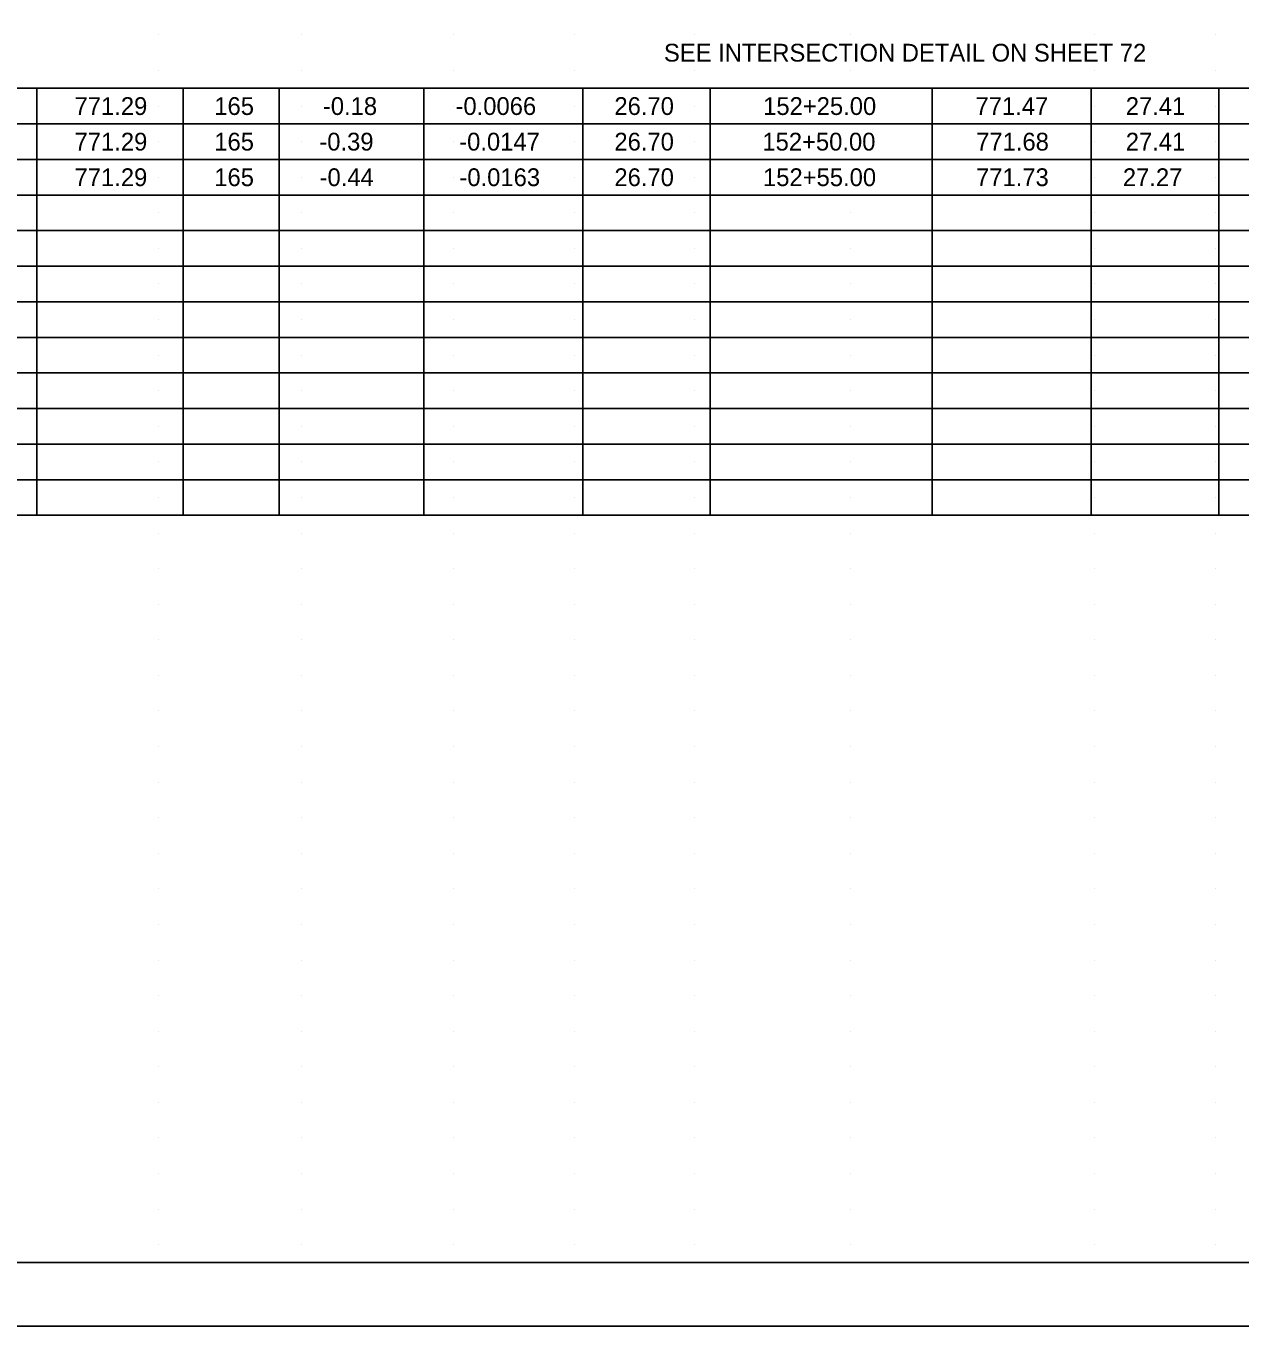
# Model space of a CAD drawing. Extents: x -15.4 to 18.6, y -12.6 to 9.4.
# Drawn here: x -5.6 to 3.96, y -12.61 to -2.38 of the extents above; entities that cross this region are included whole.
import ezdxf

# ---------------------------------------------------------------- set-up
doc = ezdxf.new("R2010")
doc.units = 0
for name, color, linetype in [('SH_Border', 7, 'Continuous'), ('SH_Cut_Line', 7, 'Continuous'), ('SH_Data', 7, 'Continuous'), ('SH_Text', 7, 'Continuous')]:
    doc.layers.add(name, color=color, linetype=linetype)

msp = doc.modelspace()

# ---------------------------------------------------------------- linework, layer by layer
at = {"layer": 'SH_Border'}
msp.add_lwpolyline([(-13.357, 8.888), (18.143, 8.888), (18.143, -12.112), (-13.357, -12.112)], close=True, dxfattribs=at)
at = {"layer": 'SH_Cut_Line'}
msp.add_lwpolyline([(-15.357, -12.612), (18.643, -12.612), (18.643, 9.388), (-15.357, 9.388)], close=True, dxfattribs=at)
at = {"layer": 'SH_Data'}
for p, q in [((-4.557, -2.452), (-4.557, -2.452)), ((-3.432, -2.452), (-3.432, -2.452)), ((-2.232, -2.452), (-2.232, -2.452)), ((-1.282, -2.452), (-1.282, -2.452)), ((-0.332, -2.452), (-0.332, -2.452)), ((0.893, -2.452), (0.893, -2.452)), ((2.818, -2.452), (2.818, -2.452)), ((3.768, -2.452), (3.768, -2.452)), ((-4.557, -2.732), (-4.557, -2.732)), ((-3.432, -2.732), (-3.432, -2.732)), ((-2.232, -2.732), (-2.232, -2.732)), ((-1.282, -2.732), (-1.282, -2.732)), ((-0.332, -2.732), (-0.332, -2.732)), ((0.893, -2.732), (0.893, -2.732)), ((2.818, -2.732), (2.818, -2.732)), ((3.768, -2.732), (3.768, -2.732)), ((-10.059, -2.872), (13.939, -2.872)), ((-5.513, -2.872), (-5.513, -6.232)), ((-4.36, -2.872), (-4.36, -6.232)), ((-3.603, -2.872), (-3.603, -6.232)), ((-2.466, -2.872), (-2.466, -6.232)), ((-1.214, -2.872), (-1.214, -6.232)), ((-0.21, -2.872), (-0.21, -6.232)), ((1.536, -2.872), (1.536, -6.232)), ((2.788, -2.872), (2.788, -6.232)), ((3.793, -2.872), (3.793, -6.232)), ((-4.557, -3.012), (-4.557, -3.012)), ((-3.432, -3.012), (-3.432, -3.012)), ((-2.232, -3.012), (-2.232, -3.012)), ((-1.282, -3.012), (-1.282, -3.012)), ((-0.332, -3.012), (-0.332, -3.012)), ((0.893, -3.012), (0.893, -3.012)), ((2.818, -3.012), (2.818, -3.012)), ((3.768, -3.012), (3.768, -3.012)), ((-10.059, -3.152), (13.939, -3.152)), ((-4.557, -3.292), (-4.557, -3.292)), ((-3.432, -3.292), (-3.432, -3.292)), ((-2.232, -3.292), (-2.232, -3.292)), ((-1.282, -3.292), (-1.282, -3.292)), ((-0.332, -3.292), (-0.332, -3.292)), ((0.893, -3.292), (0.893, -3.292)), ((2.818, -3.292), (2.818, -3.292)), ((3.768, -3.292), (3.768, -3.292)), ((-10.059, -3.432), (13.939, -3.432)), ((-4.557, -3.572), (-4.557, -3.572)), ((-3.432, -3.572), (-3.432, -3.572)), ((-2.232, -3.572), (-2.232, -3.572)), ((-1.282, -3.572), (-1.282, -3.572)), ((-0.332, -3.572), (-0.332, -3.572)), ((0.893, -3.572), (0.893, -3.572)), ((2.818, -3.572), (2.818, -3.572)), ((3.768, -3.572), (3.768, -3.572)), ((-10.059, -3.712), (13.939, -3.712)), ((-4.557, -3.852), (-4.557, -3.852)), ((-3.432, -3.852), (-3.432, -3.852)), ((-2.232, -3.852), (-2.232, -3.852)), ((-1.282, -3.852), (-1.282, -3.852)), ((-0.332, -3.852), (-0.332, -3.852)), ((0.893, -3.852), (0.893, -3.852)), ((2.818, -3.852), (2.818, -3.852)), ((3.768, -3.852), (3.768, -3.852)), ((-10.059, -3.992), (13.939, -3.992)), ((-4.557, -4.132), (-4.557, -4.132)), ((-3.432, -4.132), (-3.432, -4.132)), ((-2.232, -4.132), (-2.232, -4.132)), ((-1.282, -4.132), (-1.282, -4.132)), ((-0.332, -4.132), (-0.332, -4.132)), ((0.893, -4.132), (0.893, -4.132)), ((2.818, -4.132), (2.818, -4.132)), ((3.768, -4.132), (3.768, -4.132)), ((-10.059, -4.272), (13.939, -4.272)), ((-4.557, -4.412), (-4.557, -4.412)), ((-3.432, -4.412), (-3.432, -4.412)), ((-2.232, -4.412), (-2.232, -4.412)), ((-1.282, -4.412), (-1.282, -4.412)), ((-0.332, -4.412), (-0.332, -4.412)), ((0.893, -4.412), (0.893, -4.412)), ((2.818, -4.412), (2.818, -4.412)), ((3.768, -4.412), (3.768, -4.412)), ((-10.059, -4.552), (13.939, -4.552)), ((-4.557, -4.692), (-4.557, -4.692)), ((-3.432, -4.692), (-3.432, -4.692)), ((-2.232, -4.692), (-2.232, -4.692)), ((-1.282, -4.692), (-1.282, -4.692)), ((-0.332, -4.692), (-0.332, -4.692)), ((0.893, -4.692), (0.893, -4.692)), ((2.818, -4.692), (2.818, -4.692)), ((3.768, -4.692), (3.768, -4.692)), ((-10.059, -4.832), (13.939, -4.832)), ((-4.557, -4.972), (-4.557, -4.972)), ((-3.432, -4.972), (-3.432, -4.972)), ((-2.232, -4.972), (-2.232, -4.972)), ((-1.282, -4.972), (-1.282, -4.972)), ((-0.332, -4.972), (-0.332, -4.972)), ((0.893, -4.972), (0.893, -4.972)), ((2.818, -4.972), (2.818, -4.972)), ((3.768, -4.972), (3.768, -4.972)), ((-10.059, -5.112), (13.939, -5.112)), ((-4.557, -5.252), (-4.557, -5.252)), ((-3.432, -5.252), (-3.432, -5.252)), ((-2.232, -5.252), (-2.232, -5.252)), ((-1.282, -5.252), (-1.282, -5.252)), ((-0.332, -5.252), (-0.332, -5.252)), ((0.893, -5.252), (0.893, -5.252)), ((2.818, -5.252), (2.818, -5.252)), ((3.768, -5.252), (3.768, -5.252)), ((-10.059, -5.392), (13.939, -5.392)), ((-4.557, -5.532), (-4.557, -5.532)), ((-3.432, -5.532), (-3.432, -5.532)), ((-2.232, -5.532), (-2.232, -5.532)), ((-1.282, -5.532), (-1.282, -5.532)), ((-0.332, -5.532), (-0.332, -5.532)), ((0.893, -5.532), (0.893, -5.532)), ((2.818, -5.532), (2.818, -5.532)), ((3.768, -5.532), (3.768, -5.532)), ((-10.059, -5.672), (13.939, -5.672)), ((-4.557, -5.812), (-4.557, -5.812)), ((-3.432, -5.812), (-3.432, -5.812)), ((-2.232, -5.812), (-2.232, -5.812)), ((-1.282, -5.812), (-1.282, -5.812)), ((-0.332, -5.812), (-0.332, -5.812)), ((0.893, -5.812), (0.893, -5.812)), ((2.818, -5.812), (2.818, -5.812)), ((3.768, -5.812), (3.768, -5.812)), ((-10.059, -5.952), (13.939, -5.952)), ((-4.557, -6.092), (-4.557, -6.092)), ((-3.432, -6.092), (-3.432, -6.092)), ((-2.232, -6.092), (-2.232, -6.092)), ((-1.282, -6.092), (-1.282, -6.092)), ((-0.332, -6.092), (-0.332, -6.092)), ((0.893, -6.092), (0.893, -6.092)), ((2.818, -6.092), (2.818, -6.092)), ((3.768, -6.092), (3.768, -6.092)), ((-10.059, -6.232), (13.939, -6.232)), ((-4.557, -6.372), (-4.557, -6.372)), ((-3.432, -6.372), (-3.432, -6.372)), ((-2.232, -6.372), (-2.232, -6.372)), ((-1.282, -6.372), (-1.282, -6.372)), ((-0.332, -6.372), (-0.332, -6.372)), ((0.893, -6.372), (0.893, -6.372)), ((2.818, -6.372), (2.818, -6.372)), ((3.768, -6.372), (3.768, -6.372)), ((-4.557, -6.652), (-4.557, -6.652)), ((-3.432, -6.652), (-3.432, -6.652)), ((-2.232, -6.652), (-2.232, -6.652)), ((-1.282, -6.652), (-1.282, -6.652)), ((-0.332, -6.652), (-0.332, -6.652)), ((0.893, -6.652), (0.893, -6.652)), ((2.818, -6.652), (2.818, -6.652)), ((3.768, -6.652), (3.768, -6.652)), ((-4.557, -6.932), (-4.557, -6.932)), ((-3.432, -6.932), (-3.432, -6.932)), ((-2.232, -6.932), (-2.232, -6.932)), ((-1.282, -6.932), (-1.282, -6.932)), ((-0.332, -6.932), (-0.332, -6.932)), ((0.893, -6.932), (0.893, -6.932)), ((2.818, -6.932), (2.818, -6.932)), ((3.768, -6.932), (3.768, -6.932)), ((-4.557, -7.212), (-4.557, -7.212)), ((-3.432, -7.212), (-3.432, -7.212)), ((-2.232, -7.212), (-2.232, -7.212)), ((-1.282, -7.212), (-1.282, -7.212)), ((-0.332, -7.212), (-0.332, -7.212)), ((0.893, -7.212), (0.893, -7.212)), ((2.818, -7.212), (2.818, -7.212)), ((3.768, -7.212), (3.768, -7.212)), ((-4.557, -7.492), (-4.557, -7.492)), ((-3.432, -7.492), (-3.432, -7.492)), ((-2.232, -7.492), (-2.232, -7.492)), ((-1.282, -7.492), (-1.282, -7.492)), ((-0.332, -7.492), (-0.332, -7.492)), ((0.893, -7.492), (0.893, -7.492)), ((2.818, -7.492), (2.818, -7.492)), ((3.768, -7.492), (3.768, -7.492)), ((-4.557, -7.772), (-4.557, -7.772)), ((-3.432, -7.772), (-3.432, -7.772)), ((-2.232, -7.772), (-2.232, -7.772)), ((-1.282, -7.772), (-1.282, -7.772)), ((-0.332, -7.772), (-0.332, -7.772)), ((0.893, -7.772), (0.893, -7.772)), ((2.818, -7.772), (2.818, -7.772)), ((3.768, -7.772), (3.768, -7.772)), ((-4.557, -8.052), (-4.557, -8.052)), ((-3.432, -8.052), (-3.432, -8.052)), ((-2.232, -8.052), (-2.232, -8.052)), ((-1.282, -8.052), (-1.282, -8.052)), ((-0.332, -8.052), (-0.332, -8.052)), ((0.893, -8.052), (0.893, -8.052)), ((2.818, -8.052), (2.818, -8.052)), ((3.768, -8.052), (3.768, -8.052)), ((-4.557, -8.332), (-4.557, -8.332)), ((-3.432, -8.332), (-3.432, -8.332)), ((-2.232, -8.332), (-2.232, -8.332)), ((-1.282, -8.332), (-1.282, -8.332)), ((-0.332, -8.332), (-0.332, -8.332)), ((0.893, -8.332), (0.893, -8.332)), ((2.818, -8.332), (2.818, -8.332)), ((3.768, -8.332), (3.768, -8.332)), ((-4.557, -8.612), (-4.557, -8.612)), ((-3.432, -8.612), (-3.432, -8.612)), ((-2.232, -8.612), (-2.232, -8.612)), ((-1.282, -8.612), (-1.282, -8.612)), ((-0.332, -8.612), (-0.332, -8.612)), ((0.893, -8.612), (0.893, -8.612)), ((2.818, -8.612), (2.818, -8.612)), ((3.768, -8.612), (3.768, -8.612)), ((-4.557, -8.892), (-4.557, -8.892)), ((-3.432, -8.892), (-3.432, -8.892)), ((-2.232, -8.892), (-2.232, -8.892)), ((-1.282, -8.892), (-1.282, -8.892)), ((-0.332, -8.892), (-0.332, -8.892)), ((0.893, -8.892), (0.893, -8.892)), ((2.818, -8.892), (2.818, -8.892)), ((3.768, -8.892), (3.768, -8.892)), ((-4.557, -9.172), (-4.557, -9.172)), ((-3.432, -9.172), (-3.432, -9.172)), ((-2.232, -9.172), (-2.232, -9.172)), ((-1.282, -9.172), (-1.282, -9.172)), ((-0.332, -9.172), (-0.332, -9.172)), ((0.893, -9.172), (0.893, -9.172)), ((2.818, -9.172), (2.818, -9.172)), ((3.768, -9.172), (3.768, -9.172)), ((-4.557, -9.452), (-4.557, -9.452)), ((-3.432, -9.452), (-3.432, -9.452)), ((-2.232, -9.452), (-2.232, -9.452)), ((-1.282, -9.452), (-1.282, -9.452)), ((-0.332, -9.452), (-0.332, -9.452)), ((0.893, -9.452), (0.893, -9.452)), ((2.818, -9.452), (2.818, -9.452)), ((3.768, -9.452), (3.768, -9.452)), ((-4.557, -9.732), (-4.557, -9.732)), ((-3.432, -9.732), (-3.432, -9.732)), ((-2.232, -9.732), (-2.232, -9.732)), ((-1.282, -9.732), (-1.282, -9.732)), ((-0.332, -9.732), (-0.332, -9.732)), ((0.893, -9.732), (0.893, -9.732)), ((2.818, -9.732), (2.818, -9.732)), ((3.768, -9.732), (3.768, -9.732)), ((-4.557, -10.012), (-4.557, -10.012)), ((-3.432, -10.012), (-3.432, -10.012)), ((-2.232, -10.012), (-2.232, -10.012)), ((-1.282, -10.012), (-1.282, -10.012)), ((-0.332, -10.012), (-0.332, -10.012)), ((0.893, -10.012), (0.893, -10.012)), ((2.818, -10.012), (2.818, -10.012)), ((3.768, -10.012), (3.768, -10.012)), ((-4.557, -10.292), (-4.557, -10.292)), ((-3.432, -10.292), (-3.432, -10.292)), ((-2.232, -10.292), (-2.232, -10.292)), ((-1.282, -10.292), (-1.282, -10.292)), ((-0.332, -10.292), (-0.332, -10.292)), ((0.893, -10.292), (0.893, -10.292)), ((2.818, -10.292), (2.818, -10.292)), ((3.768, -10.292), (3.768, -10.292)), ((-4.557, -10.572), (-4.557, -10.572)), ((-3.432, -10.572), (-3.432, -10.572)), ((-2.232, -10.572), (-2.232, -10.572)), ((-1.282, -10.572), (-1.282, -10.572)), ((-0.332, -10.572), (-0.332, -10.572)), ((0.893, -10.572), (0.893, -10.572)), ((2.818, -10.572), (2.818, -10.572)), ((3.768, -10.572), (3.768, -10.572)), ((-4.557, -10.852), (-4.557, -10.852)), ((-3.432, -10.852), (-3.432, -10.852)), ((-2.232, -10.852), (-2.232, -10.852)), ((-1.282, -10.852), (-1.282, -10.852)), ((-0.332, -10.852), (-0.332, -10.852)), ((0.893, -10.852), (0.893, -10.852)), ((2.818, -10.852), (2.818, -10.852)), ((3.768, -10.852), (3.768, -10.852)), ((-4.557, -11.132), (-4.557, -11.132)), ((-3.432, -11.132), (-3.432, -11.132)), ((-2.232, -11.132), (-2.232, -11.132)), ((-1.282, -11.132), (-1.282, -11.132)), ((-0.332, -11.132), (-0.332, -11.132)), ((0.893, -11.132), (0.893, -11.132)), ((2.818, -11.132), (2.818, -11.132)), ((3.768, -11.132), (3.768, -11.132)), ((-4.557, -11.412), (-4.557, -11.412)), ((-3.432, -11.412), (-3.432, -11.412)), ((-2.232, -11.412), (-2.232, -11.412)), ((-1.282, -11.412), (-1.282, -11.412)), ((-0.332, -11.412), (-0.332, -11.412)), ((0.893, -11.412), (0.893, -11.412)), ((2.818, -11.412), (2.818, -11.412)), ((3.768, -11.412), (3.768, -11.412)), ((-4.557, -11.692), (-4.557, -11.692)), ((-3.432, -11.692), (-3.432, -11.692)), ((-2.232, -11.692), (-2.232, -11.692)), ((-1.282, -11.692), (-1.282, -11.692)), ((-0.332, -11.692), (-0.332, -11.692)), ((0.893, -11.692), (0.893, -11.692)), ((2.818, -11.692), (2.818, -11.692)), ((3.768, -11.692), (3.768, -11.692)), ((-4.557, -11.972), (-4.557, -11.972)), ((-3.432, -11.972), (-3.432, -11.972)), ((-2.232, -11.972), (-2.232, -11.972)), ((-1.282, -11.972), (-1.282, -11.972)), ((-0.332, -11.972), (-0.332, -11.972)), ((0.893, -11.972), (0.893, -11.972)), ((2.818, -11.972), (2.818, -11.972)), ((3.768, -11.972), (3.768, -11.972))]:
    msp.add_line(p, q, dxfattribs=at)

# ---------------------------------------------------------------- texts
at = {"layer": 'SH_Text'}
for s, p in [('SEE INTERSECTION DETAIL ON SHEET 72', (-0.575, -2.662)), ('771.29', (-5.215, -3.082)), ('165', (-4.115, -3.082)), ('-0.18', (-3.26, -3.082)), ('-0.0066', (-2.216, -3.082)), ('26.70', (-0.965, -3.082)), ('152+25.00', (0.206, -3.082)), ('771.47', (1.878, -3.082)), ('27.41', (3.061, -3.082)), ('771.29', (-5.215, -3.362)), ('165', (-4.115, -3.362)), ('-0.39', (-3.288, -3.362)), ('-0.0147', (-2.187, -3.362)), ('26.70', (-0.965, -3.362)), ('152+50.00', (0.2, -3.362)), ('771.68', (1.883, -3.362)), ('27.41', (3.061, -3.362)), ('771.29', (-5.215, -3.642)), ('165', (-4.115, -3.642)), ('-0.44', (-3.286, -3.642)), ('-0.0163', (-2.185, -3.642)), ('26.70', (-0.965, -3.642)), ('152+55.00', (0.205, -3.642)), ('771.73', (1.882, -3.642)), ('27.27', (3.038, -3.642))]:
    msp.add_text(s, height=0.14, dxfattribs=at).set_placement(p)

doc.saveas('drawing.dxf')
